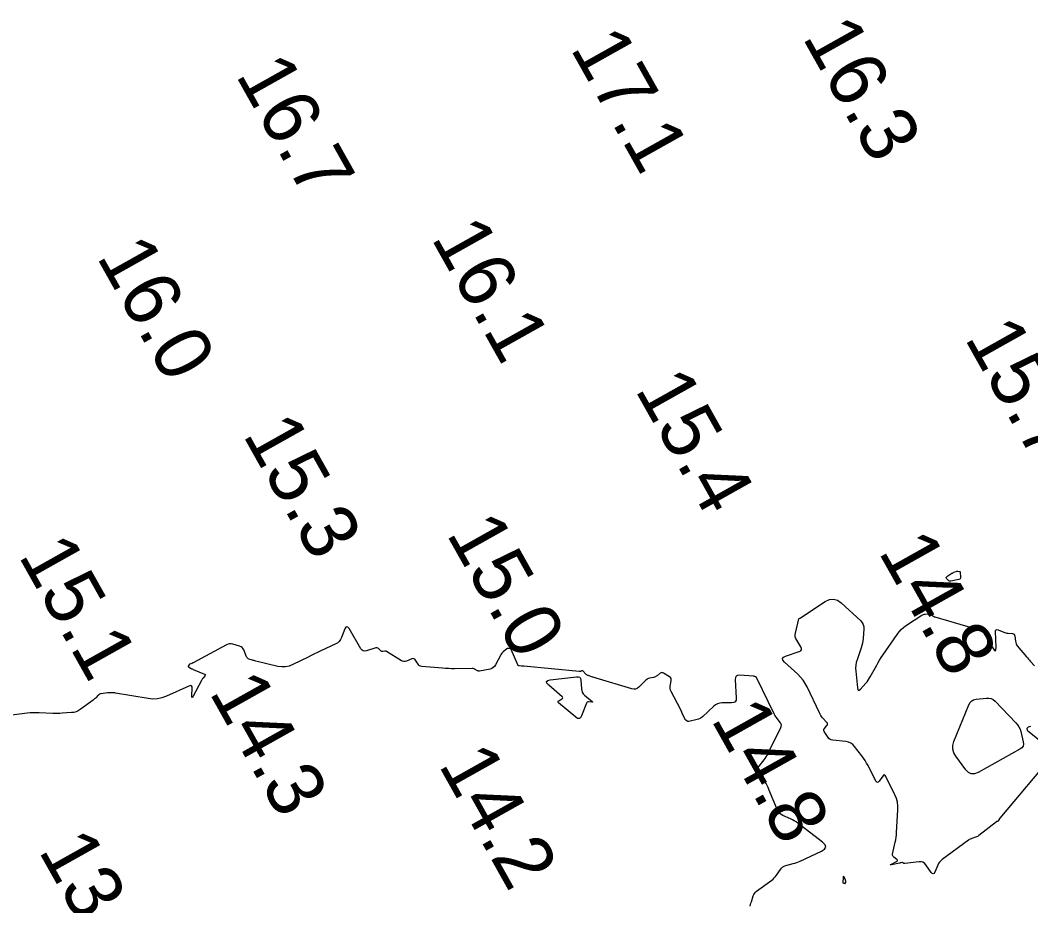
# Model space of a CAD drawing. Extents: x 1023796 to 1112670, y 656573 to 837340.
# Drawn here: x 1108641.6 to 1108730.5, y 682829.4 to 682907.4 of the extents above; entities that cross this region are included whole.
import ezdxf

# ---------------------------------------------------------------- set-up
doc = ezdxf.new("R2010")
doc.units = 0
doc.layers.add('V-CHAN-CONT-15FT', color=7, linetype='Continuous')
doc.layers.add('V-TOPO-SOUN', color=7, linetype='Continuous')

msp = doc.modelspace()

# ---------------------------------------------------------------- linework, layer by layer
at = {"layer": 'V-CHAN-CONT-15FT'}
for points in [[(1108724.013, 682858.851), (1108724.048, 682858.852), (1108724.082, 682858.848), (1108724.221, 682858.826), (1108724.251, 682858.816), (1108724.274, 682858.8), (1108724.289, 682858.776), (1108724.296, 682858.744), (1108724.329, 682858.326), (1108724.324, 682858.252), (1108724.298, 682858.195), (1108724.251, 682858.155), (1108724.181, 682858.13), (1108723.453, 682857.982), (1108723.396, 682857.977), (1108723.344, 682857.986), (1108723.296, 682858.009), (1108723.253, 682858.046), (1108723.089, 682858.222), (1108723.06, 682858.265), (1108723.053, 682858.304), (1108723.069, 682858.341), (1108723.108, 682858.375), (1108723.561, 682858.669), (1108723.603, 682858.694), (1108723.646, 682858.718), (1108723.691, 682858.738), (1108723.736, 682858.757), (1108723.947, 682858.835), (1108723.98, 682858.845)], [(1108689.311, 682847.705), (1108689.299, 682847.753), (1108689.256, 682847.803), (1108688.079, 682848.832), (1108687.926, 682849.002), (1108687.898, 682849.133), (1108687.995, 682849.226), (1108688.217, 682849.28), (1108690.54, 682849.568), (1108690.699, 682849.565), (1108690.815, 682849.511), (1108690.888, 682849.406), (1108690.919, 682849.251), (1108690.958, 682848.499), (1108690.982, 682848.339), (1108691.036, 682848.194), (1108691.12, 682848.064), (1108691.234, 682847.949), (1108691.899, 682847.395), (1108691.938, 682847.356), (1108691.946, 682847.331), (1108691.922, 682847.319), (1108691.867, 682847.321), (1108691.586, 682847.356), (1108691.521, 682847.355), (1108691.467, 682847.336), (1108691.425, 682847.298), (1108691.393, 682847.241), (1108690.96, 682846.123), (1108690.868, 682845.959), (1108690.753, 682845.883), (1108690.617, 682845.895), (1108690.457, 682845.996), (1108688.955, 682847.273), (1108688.911, 682847.322), (1108688.899, 682847.37), (1108688.919, 682847.414), (1108688.97, 682847.456), (1108689.239, 682847.618), (1108689.291, 682847.66)], [(1108729.461, 682845.153), (1108729.554, 682844.953), (1108729.621, 682844.737), (1108729.837, 682843.847), (1108729.86, 682843.638), (1108729.818, 682843.458), (1108729.713, 682843.305), (1108729.545, 682843.18), (1108725.864, 682841.139), (1108725.552, 682841.019), (1108725.267, 682841.019), (1108725.007, 682841.138), (1108724.774, 682841.377), (1108723.893, 682842.574), (1108723.718, 682842.879), (1108723.633, 682843.195), (1108723.638, 682843.522), (1108723.733, 682843.861), (1108725.056, 682847.103), (1108725.16, 682847.291), (1108725.299, 682847.433), (1108725.473, 682847.53), (1108725.682, 682847.58), (1108726.589, 682847.687), (1108726.807, 682847.691), (1108727.008, 682847.646), (1108727.192, 682847.553), (1108727.36, 682847.413), (1108729.195, 682845.512), (1108729.341, 682845.34)], [(1108714.007, 682831.391), (1108714.003, 682831.399), (1108714.002, 682831.409), (1108714.014, 682831.925), (1108714.019, 682831.978), (1108714.029, 682831.997), (1108714.045, 682831.982), (1108714.066, 682831.934), (1108714.193, 682831.592), (1108714.2, 682831.566), (1108714.201, 682831.541), (1108714.196, 682831.516), (1108714.185, 682831.491), (1108714.107, 682831.349), (1108714.106, 682831.347), (1108714.104, 682831.346), (1108714.102, 682831.347), (1108714.1, 682831.348), (1108714.092, 682831.357), (1108714.089, 682831.359), (1108714.087, 682831.36), (1108714.084, 682831.362), (1108714.082, 682831.363), (1108714.023, 682831.38), (1108714.014, 682831.384)]]:
    msp.add_lwpolyline(points, close=True, dxfattribs=at)
for points in [[(1108731.328, 682841.338), (1108727.783, 682837.101), (1108727.762, 682837.075), (1108727.742, 682837.049), (1108727.723, 682837.022), (1108727.705, 682836.995), (1108727.611, 682836.85), (1108727.603, 682836.84), (1108727.594, 682836.833), (1108727.584, 682836.828), (1108727.572, 682836.826), (1108727.523, 682836.82), (1108727.511, 682836.818), (1108727.499, 682836.814), (1108727.489, 682836.809), (1108727.478, 682836.802), (1108725.942, 682835.593), (1108725.873, 682835.544), (1108725.801, 682835.501), (1108725.725, 682835.465), (1108725.645, 682835.436), (1108725.32, 682835.332), (1108725.24, 682835.303), (1108725.163, 682835.268), (1108725.09, 682835.226), (1108725.019, 682835.179), (1108722.708, 682833.472), (1108722.584, 682833.368), (1108722.477, 682833.25), (1108722.386, 682833.119), (1108722.311, 682832.975), (1108722.048, 682832.371), (1108721.978, 682832.256), (1108721.902, 682832.213), (1108721.819, 682832.241), (1108721.73, 682832.341), (1108721.269, 682833.013), (1108721.151, 682833.148), (1108721.013, 682833.237), (1108720.854, 682833.281), (1108720.675, 682833.279), (1108719.405, 682833.117), (1108719.383, 682833.116), (1108719.361, 682833.119), (1108719.341, 682833.126), (1108719.321, 682833.137), (1108719.243, 682833.188), (1108719.224, 682833.198), (1108719.203, 682833.205), (1108719.182, 682833.207), (1108719.159, 682833.204), (1108719.056, 682833.184), (1108719.031, 682833.179), (1108719.006, 682833.174), (1108718.981, 682833.168), (1108718.956, 682833.163), (1108718.252, 682833.013), (1108718.168, 682832.998), (1108718.136, 682833.002), (1108718.158, 682833.025), (1108718.233, 682833.066), (1108718.693, 682833.295), (1108718.75, 682833.335), (1108718.772, 682833.377), (1108718.759, 682833.423), (1108718.709, 682833.472), (1108718.44, 682833.676), (1108718.383, 682833.731), (1108718.348, 682833.793), (1108718.334, 682833.864), (1108718.341, 682833.942), (1108718.579, 682835.014), (1108718.62, 682835.221), (1108718.653, 682835.428), (1108718.678, 682835.637), (1108718.694, 682835.847), (1108718.81, 682837.839), (1108718.808, 682838.182), (1108718.763, 682838.517), (1108718.675, 682838.842), (1108718.544, 682839.159), (1108717.746, 682840.79), (1108717.684, 682840.884), (1108717.617, 682840.918), (1108717.545, 682840.894), (1108717.469, 682840.811), (1108717.156, 682840.362), (1108717.08, 682840.279), (1108717.007, 682840.254), (1108716.939, 682840.288), (1108716.874, 682840.381), (1108716.179, 682841.736), (1108716.058, 682841.959), (1108715.927, 682842.176), (1108715.787, 682842.387), (1108715.637, 682842.592), (1108714.998, 682843.423), (1108714.841, 682843.592), (1108714.661, 682843.72), (1108714.457, 682843.806), (1108714.231, 682843.851), (1108713.069, 682843.973), (1108712.944, 682843.998), (1108712.835, 682844.049), (1108712.741, 682844.124), (1108712.661, 682844.223), (1108712.322, 682844.751), (1108712.289, 682844.821), (1108712.281, 682844.889), (1108712.298, 682844.956), (1108712.341, 682845.02), (1108712.562, 682845.276), (1108712.603, 682845.339), (1108712.617, 682845.403), (1108712.602, 682845.466), (1108712.56, 682845.529), (1108712.172, 682845.96), (1108712.092, 682846.056), (1108712.02, 682846.156), (1108711.955, 682846.262), (1108711.899, 682846.372), (1108710.826, 682848.66), (1108710.661, 682848.972), (1108710.468, 682849.263), (1108710.247, 682849.533), (1108709.998, 682849.782), (1108708.818, 682850.855), (1108708.676, 682851.024), (1108708.647, 682851.169), (1108708.732, 682851.29), (1108708.931, 682851.387), (1108710.132, 682851.786), (1108710.265, 682851.852), (1108710.333, 682851.941), (1108710.337, 682852.054), (1108710.275, 682852.189), (1108709.9, 682852.775), (1108709.823, 682852.925), (1108709.78, 682853.08), (1108709.77, 682853.241), (1108709.795, 682853.407), (1108710.101, 682854.658), (1108710.105, 682854.67), (1108710.112, 682854.681), (1108710.121, 682854.689), (1108710.132, 682854.695), (1108710.182, 682854.717), (1108710.194, 682854.723), (1108710.206, 682854.729), (1108710.218, 682854.736), (1108710.23, 682854.743), (1108712.421, 682856.174), (1108712.784, 682856.347), (1108713.137, 682856.386), (1108713.478, 682856.29), (1108713.809, 682856.06), (1108715.542, 682854.471), (1108715.675, 682854.321), (1108715.765, 682854.154), (1108715.812, 682853.97), (1108715.816, 682853.769), (1108715.745, 682852.933), (1108715.72, 682852.725), (1108715.684, 682852.519), (1108715.635, 682852.317), (1108715.573, 682852.117), (1108715.212, 682851.06), (1108715.143, 682850.815), (1108715.101, 682850.568), (1108715.085, 682850.318), (1108715.096, 682850.065), (1108715.24, 682848.573), (1108715.269, 682848.439), (1108715.324, 682848.379), (1108715.403, 682848.393), (1108715.508, 682848.482), (1108715.978, 682848.987), (1108716.092, 682849.116), (1108716.196, 682849.252), (1108716.291, 682849.394), (1108716.377, 682849.543), (1108716.941, 682850.587), (1108717.066, 682850.81), (1108717.196, 682851.029), (1108717.332, 682851.244), (1108717.473, 682851.457), (1108718.731, 682853.287), (1108718.908, 682853.52), (1108719.106, 682853.734), (1108719.323, 682853.926), (1108719.56, 682854.099), (1108720.917, 682854.989), (1108720.982, 682855.026), (1108721.05, 682855.054), (1108721.122, 682855.072), (1108721.196, 682855.082), (1108721.556, 682855.104), (1108721.603, 682855.103), (1108721.647, 682855.093), (1108721.689, 682855.075), (1108721.728, 682855.048), (1108721.878, 682854.923), (1108721.917, 682854.894), (1108721.958, 682854.869), (1108722.001, 682854.848), (1108722.047, 682854.833), (1108725.474, 682853.828), (1108725.546, 682853.808), (1108725.618, 682853.79), (1108725.69, 682853.774), (1108725.763, 682853.759), (1108726.056, 682853.706), (1108726.125, 682853.687), (1108726.185, 682853.655), (1108726.236, 682853.61), (1108726.279, 682853.553), (1108727.179, 682852.051), (1108727.301, 682851.879), (1108727.386, 682851.835), (1108727.434, 682851.918), (1108727.444, 682852.129), (1108727.399, 682853.531), (1108727.41, 682853.633), (1108727.451, 682853.693), (1108727.521, 682853.711), (1108727.62, 682853.686), (1108728.126, 682853.486), (1108728.216, 682853.454), (1108728.309, 682853.428), (1108728.403, 682853.409), (1108728.499, 682853.396), (1108728.884, 682853.358), (1108728.97, 682853.338), (1108729.035, 682853.296), (1108729.077, 682853.232), (1108729.099, 682853.146), (1108729.151, 682852.68), (1108729.17, 682852.573), (1108729.204, 682852.473), (1108729.253, 682852.378), (1108729.316, 682852.29), (1108730.115, 682851.316), (1108730.2, 682851.215), (1108730.285, 682851.115), (1108730.373, 682851.017), (1108730.461, 682850.919), (1108730.819, 682850.533)], [(1108705.795, 682829.383), (1108705.835, 682829.509), (1108705.875, 682829.636), (1108705.916, 682829.762), (1108706.079, 682830.268), (1108706.128, 682830.388), (1108706.193, 682830.497), (1108706.275, 682830.593), (1108706.374, 682830.678), (1108707.705, 682831.664), (1108707.823, 682831.76), (1108707.933, 682831.865), (1108708.033, 682831.978), (1108708.124, 682832.101), (1108708.468, 682832.61), (1108708.562, 682832.726), (1108708.672, 682832.82), (1108708.797, 682832.892), (1108708.938, 682832.942), (1108709.591, 682833.114), (1108709.748, 682833.159), (1108709.903, 682833.211), (1108710.055, 682833.269), (1108710.205, 682833.335), (1108712.072, 682834.196), (1108712.348, 682834.372), (1108712.455, 682834.567), (1108712.393, 682834.781), (1108712.163, 682835.013), (1108709.989, 682836.682), (1108709.841, 682836.789), (1108709.688, 682836.886), (1108709.529, 682836.973), (1108709.365, 682837.051), (1108708.696, 682837.344), (1108708.541, 682837.429), (1108708.41, 682837.538), (1108708.303, 682837.671), (1108708.22, 682837.827), (1108707.458, 682839.638), (1108707.383, 682839.811), (1108707.305, 682839.982), (1108707.224, 682840.152), (1108707.139, 682840.321), (1108706.647, 682841.277), (1108706.633, 682841.301), (1108706.617, 682841.325), (1108706.599, 682841.347), (1108706.58, 682841.368), (1108706.499, 682841.449), (1108706.483, 682841.47), (1108706.477, 682841.491), (1108706.481, 682841.513), (1108706.493, 682841.535), (1108707.04, 682842.244), (1108707.134, 682842.371), (1108707.221, 682842.503), (1108707.301, 682842.64), (1108707.374, 682842.78), (1108708.506, 682845.085), (1108708.544, 682845.192), (1108708.551, 682845.296), (1108708.526, 682845.398), (1108708.47, 682845.497), (1108708.183, 682845.887), (1108708.114, 682845.985), (1108708.049, 682846.087), (1108707.989, 682846.191), (1108707.933, 682846.299), (1108706.356, 682849.505), (1108706.342, 682849.527), (1108706.325, 682849.545), (1108706.304, 682849.558), (1108706.28, 682849.568), (1108706.177, 682849.598), (1108706.151, 682849.605), (1108706.124, 682849.61), (1108706.098, 682849.614), (1108706.071, 682849.617), (1108704.886, 682849.697), (1108704.707, 682849.683), (1108704.582, 682849.615), (1108704.511, 682849.491), (1108704.495, 682849.312), (1108704.58, 682847.681), (1108704.563, 682847.496), (1108704.49, 682847.364), (1108704.362, 682847.284), (1108704.178, 682847.257), (1108703.33, 682847.253), (1108703.126, 682847.234), (1108702.935, 682847.179), (1108702.759, 682847.088), (1108702.598, 682846.961), (1108701.614, 682846.037), (1108701.509, 682845.95), (1108701.394, 682845.88), (1108701.271, 682845.826), (1108701.139, 682845.788), (1108700.399, 682845.629), (1108700.361, 682845.625), (1108700.326, 682845.628), (1108700.292, 682845.64), (1108700.261, 682845.66), (1108700.137, 682845.754), (1108700.108, 682845.779), (1108700.082, 682845.807), (1108700.061, 682845.838), (1108700.044, 682845.872), (1108699.838, 682846.354), (1108699.798, 682846.446), (1108699.755, 682846.537), (1108699.711, 682846.627), (1108699.666, 682846.716), (1108698.852, 682848.266), (1108698.805, 682848.375), (1108698.778, 682848.487), (1108698.769, 682848.602), (1108698.78, 682848.72), (1108698.863, 682849.197), (1108698.868, 682849.31), (1108698.842, 682849.408), (1108698.786, 682849.493), (1108698.698, 682849.564), (1108698.189, 682849.88), (1108698.114, 682849.915), (1108698.04, 682849.924), (1108697.968, 682849.907), (1108697.897, 682849.866), (1108697.615, 682849.65), (1108697.542, 682849.6), (1108697.466, 682849.56), (1108697.385, 682849.528), (1108697.3, 682849.505), (1108696.94, 682849.427), (1108696.854, 682849.403), (1108696.774, 682849.367), (1108696.7, 682849.32), (1108696.633, 682849.262), (1108695.997, 682848.636), (1108695.864, 682848.532), (1108695.72, 682848.473), (1108695.565, 682848.458), (1108695.399, 682848.488), (1108692.249, 682849.433), (1108692.167, 682849.458), (1108692.085, 682849.484), (1108692.003, 682849.511), (1108691.921, 682849.538), (1108691.562, 682849.659), (1108691.499, 682849.684), (1108691.439, 682849.717), (1108691.384, 682849.756), (1108691.334, 682849.802), (1108691.07, 682850.072), (1108691.056, 682850.083), (1108691.041, 682850.089), (1108691.025, 682850.089), (1108691.008, 682850.083), (1108690.931, 682850.045), (1108690.917, 682850.039), (1108690.903, 682850.035), (1108690.888, 682850.031), (1108690.874, 682850.029), (1108690.814, 682850.022), (1108690.799, 682850.02), (1108690.784, 682850.02), (1108690.77, 682850.02), (1108690.755, 682850.021), (1108685.886, 682850.481), (1108685.836, 682850.485), (1108685.787, 682850.49), (1108685.737, 682850.494), (1108685.687, 682850.497), (1108685.488, 682850.512), (1108685.442, 682850.522), (1108685.403, 682850.541), (1108685.372, 682850.571), (1108685.349, 682850.612), (1108684.775, 682851.975), (1108684.758, 682852.005), (1108684.736, 682852.027), (1108684.708, 682852.042), (1108684.674, 682852.049), (1108684.529, 682852.062), (1108684.493, 682852.062), (1108684.46, 682852.056), (1108684.429, 682852.042), (1108684.4, 682852.022), (1108684.071, 682851.747), (1108684.01, 682851.691), (1108683.955, 682851.63), (1108683.907, 682851.563), (1108683.866, 682851.491), (1108683.409, 682850.612), (1108683.319, 682850.474), (1108683.207, 682850.367), (1108683.072, 682850.289), (1108682.915, 682850.241), (1108682, 682850.061), (1108681.953, 682850.056), (1108681.908, 682850.059), (1108681.864, 682850.07), (1108681.821, 682850.09), (1108681.608, 682850.213), (1108681.589, 682850.224), (1108681.569, 682850.233), (1108681.549, 682850.241), (1108681.528, 682850.249), (1108681.445, 682850.276), (1108681.424, 682850.282), (1108681.402, 682850.286), (1108681.381, 682850.288), (1108681.359, 682850.289), (1108679.794, 682850.271), (1108679.525, 682850.271), (1108679.258, 682850.277), (1108678.99, 682850.29), (1108678.723, 682850.309), (1108676.912, 682850.462), (1108676.811, 682850.482), (1108676.723, 682850.522), (1108676.647, 682850.582), (1108676.584, 682850.663), (1108676.357, 682851.029), (1108676.294, 682851.104), (1108676.221, 682851.146), (1108676.138, 682851.155), (1108676.043, 682851.132), (1108675.56, 682850.939), (1108675.447, 682850.908), (1108675.337, 682850.903), (1108675.229, 682850.927), (1108675.124, 682850.977), (1108673.817, 682851.785), (1108673.778, 682851.805), (1108673.737, 682851.818), (1108673.694, 682851.822), (1108673.65, 682851.819), (1108673.47, 682851.792), (1108673.426, 682851.79), (1108673.386, 682851.797), (1108673.348, 682851.814), (1108673.314, 682851.841), (1108673.096, 682852.045), (1108673.047, 682852.082), (1108672.994, 682852.103), (1108672.938, 682852.107), (1108672.877, 682852.096), (1108672.047, 682851.836), (1108671.897, 682851.81), (1108671.766, 682851.833), (1108671.653, 682851.904), (1108671.559, 682852.023), (1108670.507, 682853.801), (1108670.407, 682853.931), (1108670.315, 682853.969), (1108670.229, 682853.916), (1108670.152, 682853.771), (1108669.857, 682853.008), (1108669.77, 682852.83), (1108669.654, 682852.679), (1108669.511, 682852.553), (1108669.339, 682852.453), (1108668.023, 682851.839), (1108667.743, 682851.707), (1108667.463, 682851.572), (1108667.184, 682851.436), (1108666.907, 682851.298), (1108665.572, 682850.627), (1108665.254, 682850.499), (1108664.929, 682850.431), (1108664.597, 682850.422), (1108664.258, 682850.474), (1108662.301, 682850.94), (1108662.226, 682850.959), (1108662.151, 682850.979), (1108662.076, 682851.001), (1108662.002, 682851.024), (1108661.706, 682851.12), (1108661.637, 682851.15), (1108661.58, 682851.191), (1108661.533, 682851.245), (1108661.498, 682851.311), (1108661.247, 682851.918), (1108661.186, 682852.033), (1108661.105, 682852.126), (1108661.005, 682852.198), (1108660.885, 682852.249), (1108660.284, 682852.435), (1108660.142, 682852.465), (1108660.003, 682852.466), (1108659.866, 682852.438), (1108659.733, 682852.382), (1108656.782, 682850.796), (1108656.753, 682850.781), (1108656.724, 682850.767), (1108656.694, 682850.754), (1108656.664, 682850.742), (1108656.504, 682850.68), (1108656.494, 682850.676), (1108656.484, 682850.67), (1108656.475, 682850.664), (1108656.467, 682850.657), (1108656.435, 682850.626), (1108656.428, 682850.618), (1108656.421, 682850.609), (1108656.415, 682850.6), (1108656.41, 682850.591), (1108656.363, 682850.49), (1108656.357, 682850.471), (1108656.359, 682850.455), (1108656.367, 682850.44), (1108656.383, 682850.428), (1108656.617, 682850.298), (1108656.662, 682850.273), (1108656.709, 682850.25), (1108656.756, 682850.228), (1108656.803, 682850.207), (1108657.802, 682849.782), (1108657.848, 682849.754), (1108657.869, 682849.721), (1108657.864, 682849.681), (1108657.834, 682849.637), (1108657.662, 682849.446), (1108657.621, 682849.398), (1108657.583, 682849.346), (1108657.549, 682849.293), (1108657.518, 682849.237), (1108656.804, 682847.861), (1108656.739, 682847.754), (1108656.695, 682847.725), (1108656.672, 682847.772), (1108656.67, 682847.897), (1108656.704, 682848.552), (1108656.693, 682848.687), (1108656.642, 682848.764), (1108656.552, 682848.783), (1108656.422, 682848.744), (1108654.434, 682847.846), (1108654.049, 682847.704), (1108653.656, 682847.623), (1108653.256, 682847.601), (1108652.847, 682847.64), (1108649.951, 682848.126), (1108649.894, 682848.135), (1108649.837, 682848.142), (1108649.78, 682848.147), (1108649.723, 682848.15), (1108649.494, 682848.159), (1108649.437, 682848.16), (1108649.38, 682848.159), (1108649.323, 682848.154), (1108649.266, 682848.147), (1108648.705, 682848.066), (1108648.632, 682848.05), (1108648.565, 682848.022), (1108648.504, 682847.984), (1108648.448, 682847.934), (1108648.235, 682847.714), (1108648.181, 682847.661), (1108648.124, 682847.61), (1108648.065, 682847.561), (1108648.005, 682847.515), (1108646.841, 682846.671), (1108646.67, 682846.564), (1108646.489, 682846.484), (1108646.298, 682846.43), (1108646.098, 682846.403), (1108645.278, 682846.349), (1108645.073, 682846.338), (1108644.868, 682846.333), (1108644.663, 682846.334), (1108644.458, 682846.34), (1108643.257, 682846.392), (1108642.989, 682846.398), (1108642.721, 682846.393), (1108642.454, 682846.377), (1108642.187, 682846.349), (1108639.675, 682846.034)], [(1108730.509, 682845.183), (1108730.262, 682845.112), (1108730.158, 682845.005), (1108730.196, 682844.86), (1108730.378, 682844.678), (1108731.829, 682843.528)]]:
    msp.add_lwpolyline(points, dxfattribs=at)

# ---------------------------------------------------------------- texts
at = {"layer": 'V-TOPO-SOUN'}
for s, p in [('16.3 ', (1108710.352, 682905.863)), ('17.1 ', (1108689.928, 682904.887)), ('16.7 ', (1108660.482, 682902.543)), ('16.1 ', (1108677.688, 682888.187)), ('16.0 ', (1108648.245, 682886.546)), ('15.7 ', (1108724.622, 682879.383)), ('15.4 ', (1108695.622, 682874.853)), ('15.3 ', (1108661.112, 682870.883)), ('15.0 ', (1108679.025, 682862.166)), ('14.8 ', (1108717.042, 682860.583)), ('15.1 ', (1108641.368, 682860.237)), ('14.3 ', (1108658.152, 682848.213)), ('14.8 ', (1108702.312, 682845.823)), ('14.2 ', (1108678.332, 682841.823)), ('13.8 ', (1108643.132, 682834.273))]:
    msp.add_text(s, height=5, rotation=299.30014, dxfattribs=at).set_placement(p)

doc.saveas('drawing.dxf')
